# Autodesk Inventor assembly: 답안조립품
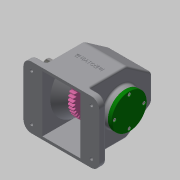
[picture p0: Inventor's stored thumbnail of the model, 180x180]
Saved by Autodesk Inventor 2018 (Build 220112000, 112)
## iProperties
Created: 2022-12
Part Number: 답안조립품
Material: 일반
Document SubType Name: Assembly
Designer: home
Author: home
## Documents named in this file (15)
- C:\Users\home\Desktop\721206V1005\답안조립품.iam
- C:\Users\home\Desktop\721206V1005\답안본체.ipt
- C:\Users\home\Desktop\721206V1005\앞커버.ipt
- C:\Users\home\Desktop\721206V1005\뒤커버.ipt
- C:\Users\home\Desktop\721206V1005\오일 실 17 x 32 x 8.ipt
- C:\Users\home\Desktop\721206V1005\베어링 6203.ipt
- C:\Users\home\Desktop\721206V1005\축.ipt
- C:\Users\home\Desktop\721206V1005\키 - 6 x 6 x 22.ipt
- C:\Users\home\Desktop\721206V1005\키 - 5 x 5 x 18.ipt
- C:\Users\home\Desktop\721206V1005\칼라.ipt
- C:\Users\home\Desktop\721206V1005\스퍼기어.ipt
- C:\Users\home\Desktop\721206V1005\V-벨트풀리.ipt
- C:\Users\home\Desktop\721206V1005\멈춤나사 - M4x10.ipt
- C:\Users\home\Desktop\721206V1005\볼트 M3 x 10.ipt
- C:\Users\home\Desktop\721206V1005\볼트 M3 x 8.ipt
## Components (9 placed, 3 different names)
1. V-벨트풀리:1
2. ISO 4762 M3 x 10:1
3. ISO 4762 M3 x 10:2
4. ISO 4762 M3 x 10:3
5. ISO 4762 M3 x 10:4
6. ISO 4762 M3 x 8:1
7. ISO 4762 M3 x 8:2
8. ISO 4762 M3 x 8:3
9. ISO 4762 M3 x 8:4
